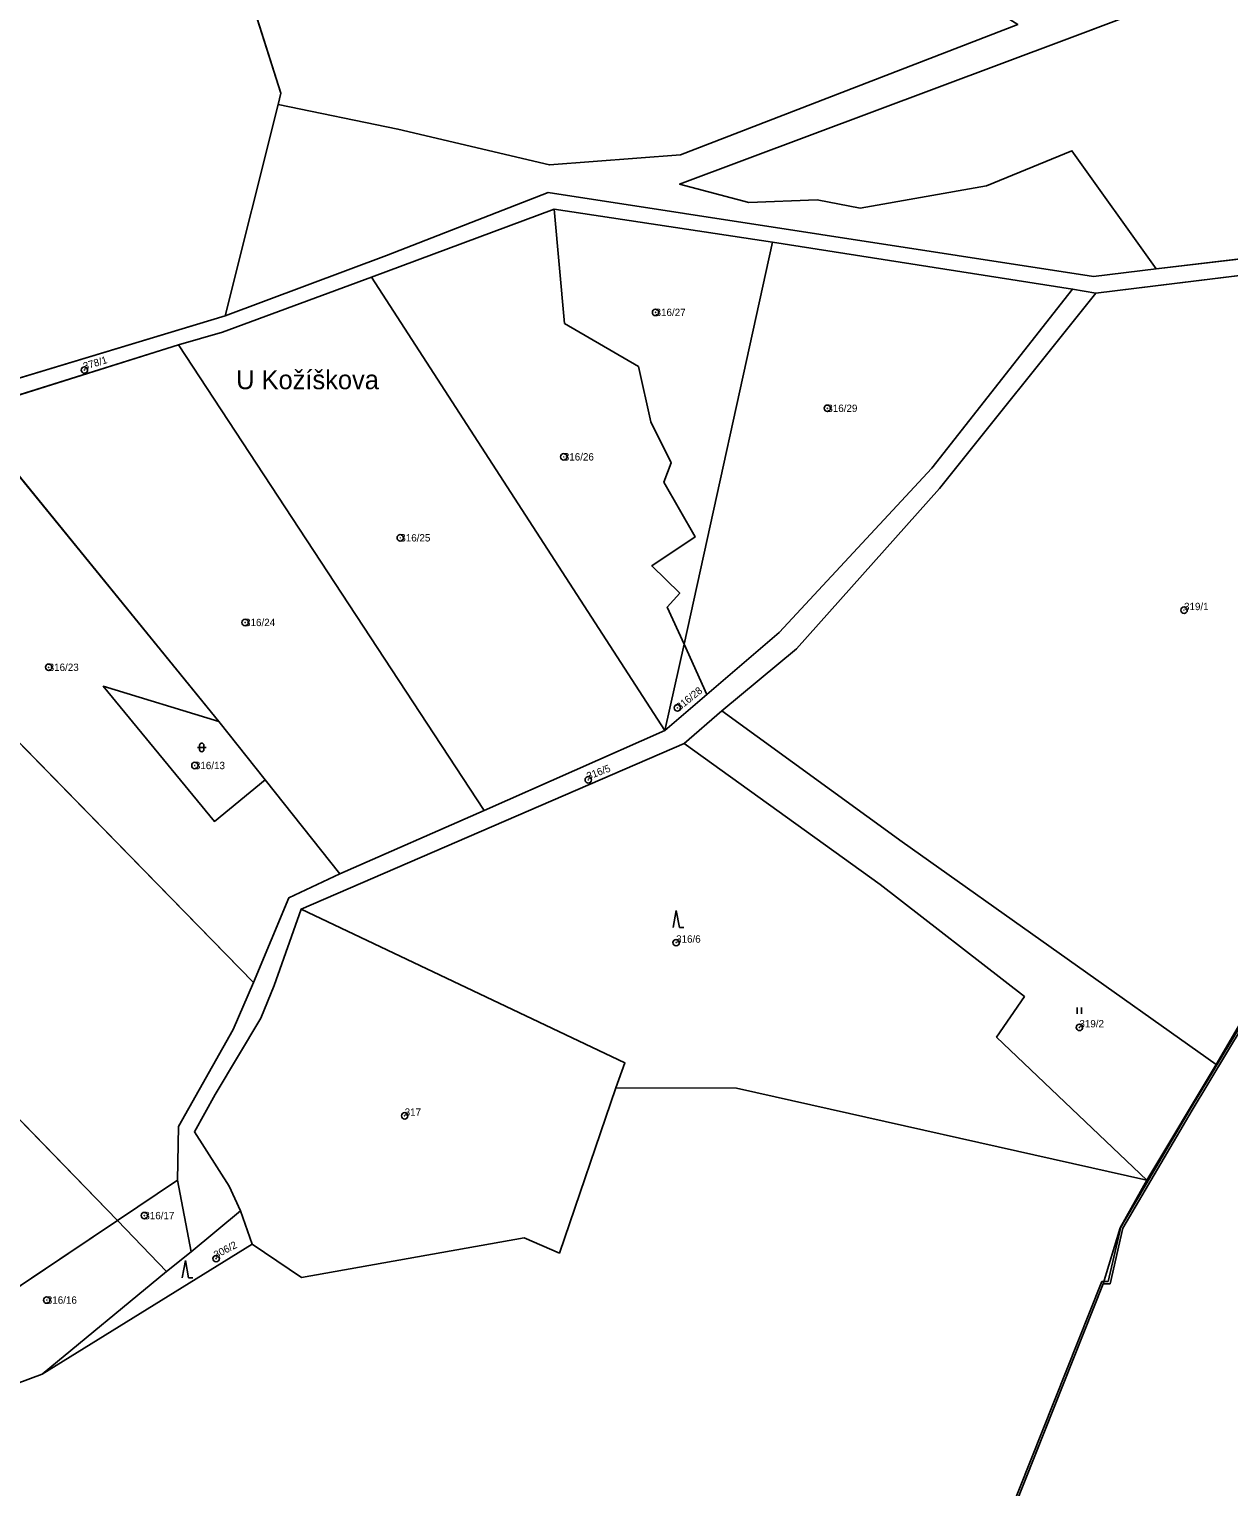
# Model space of a CAD drawing. Extents: x -652854 to -650068, y -1097661 to -1095417.
# Drawn here: x -651150.7 to -650873, y -1097423.6 to -1097086.2 of the extents above; entities that cross this region are included whole.
import ezdxf

# ---------------------------------------------------------------- set-up
doc = ezdxf.new("R2010")
doc.units = 0
for name, color, linetype in [('Definiční body parcel', 7, 'Continuous'), ('Hranice kat_ území', 7, 'Continuous'), ('Hranice parcel', 7, 'Continuous'), ('Názvy', 7, 'Continuous'), ('Obvody jako plochy', 7, 'Continuous'), ('Ostatní hranice', 7, 'Continuous'), ('Parcelní čísla', 7, 'Continuous'), ('Značky kultur', 7, 'Continuous')]:
    doc.layers.add(name, color=color, linetype=linetype)

msp = doc.modelspace()

# ---------------------------------------------------------------- linework, layer by layer
at = {"layer": 'Definiční body parcel'}
for centre, radius in [((-651005.7, -1097151.78), 0.75), ((-651005.7, -1097151.78), 0.0327), ((-651137.88, -1097165.12), 0.75), ((-651137.88, -1097165.12), 0.0327), ((-650965.95, -1097173.97), 0.75), ((-650965.95, -1097173.97), 0.0327), ((-651026.93, -1097185.21), 0.75), ((-651026.93, -1097185.21), 0.0327), ((-651064.77, -1097203.95), 0.75), ((-651064.77, -1097203.95), 0.0327), ((-651100.69, -1097223.54), 0.75), ((-650883.41, -1097220.69), 0.75), ((-650883.41, -1097220.69), 0.0327), ((-651100.69, -1097223.54), 0.0327), ((-651146.14, -1097233.91), 0.75), ((-651146.14, -1097233.91), 0.0327), ((-651000.65, -1097243.31), 0.75), ((-651000.65, -1097243.31), 0.0327), ((-651112.3, -1097256.64), 0.75), ((-651112.3, -1097256.64), 0.0327), ((-651021.27, -1097259.97), 0.75), ((-651021.27, -1097259.97), 0.0327), ((-651000.95, -1097297.64), 0.75), ((-651000.95, -1097297.64), 0.0327), ((-650907.62, -1097317.24), 0.75), ((-650907.62, -1097317.24), 0.0327), ((-651063.76, -1097337.7), 0.75), ((-651063.76, -1097337.7), 0.0327), ((-651124, -1097360.8), 0.75), ((-651124, -1097360.8), 0.0327), ((-651107.4, -1097370.77), 0.75), ((-651107.4, -1097370.77), 0.0327), ((-651146.57, -1097380.35), 0.75), ((-651146.57, -1097380.35), 0.0327)]:
    msp.add_circle(centre, radius, dxfattribs=at)
at = {"layer": 'Hranice kat_ území'}
for p, q in [((-650869.69, -1097316.78), (-650881.54, -1097336.4)), ((-650881.54, -1097336.4), (-650897.57, -1097363.68)), ((-650897.57, -1097363.68), (-650900.54, -1097376.56)), ((-650902.09, -1097376.6), (-650927.04, -1097439.3)), ((-650900.54, -1097376.56), (-650902.09, -1097376.6))]:
    msp.add_line(p, q, dxfattribs=at)
at = {"layer": 'Hranice parcel'}
for p, q in [((-651092.42, -1097101.02), (-651110.78, -1097043.06)), ((-650804.25, -1097048.49), (-650910.53, -1097088.56)), ((-650921.88, -1097085.12), (-650999.97, -1097115.32)), ((-650910.53, -1097088.56), (-651000.14, -1097122.08)), ((-651093.01, -1097103.7), (-651092.42, -1097101.02)), ((-651093.01, -1097103.7), (-651105.3, -1097152.59)), ((-651065.33, -1097109.35), (-651093.01, -1097103.7)), ((-651030.25, -1097117.65), (-651065.33, -1097109.35)), ((-650929.12, -1097122.49), (-650909.36, -1097114.39)), ((-650909.36, -1097114.39), (-650889.89, -1097141.73)), ((-650999.97, -1097115.32), (-651030.25, -1097117.65)), ((-651030.52, -1097124), (-651067.94, -1097138.65)), ((-650904.33, -1097143.45), (-651030.52, -1097124)), ((-651000.14, -1097122.08), (-650984.11, -1097126.35)), ((-650958.37, -1097127.66), (-650929.12, -1097122.49)), ((-651029.15, -1097127.92), (-651071.41, -1097143.63)), ((-651029.15, -1097127.92), (-651026.78, -1097154.34)), ((-650978.61, -1097135.56), (-651029.15, -1097127.92)), ((-650984.11, -1097126.35), (-650968.29, -1097125.74)), ((-650968.29, -1097125.74), (-650958.37, -1097127.66)), ((-650828.93, -1097134.46), (-650889.89, -1097141.73)), ((-651067.94, -1097138.65), (-651105.3, -1097152.59)), ((-650978.61, -1097135.56), (-650999.12, -1097228.58)), ((-650909.19, -1097146.38), (-650978.61, -1097135.56)), ((-650829.16, -1097138.13), (-650903.84, -1097147.32)), ((-650889.89, -1097141.73), (-650904.33, -1097143.45)), ((-651071.41, -1097143.63), (-651105.93, -1097156.36)), ((-651071.41, -1097143.63), (-651003.52, -1097248.52)), ((-650941.77, -1097187.84), (-650909.19, -1097146.38)), ((-650903.84, -1097147.32), (-650939.98, -1097192.57)), ((-650903.84, -1097147.32), (-650909.19, -1097146.38)), ((-651105.3, -1097152.59), (-651165.31, -1097170.68)), ((-651026.78, -1097154.34), (-651009.62, -1097164.32)), ((-651105.93, -1097156.36), (-651116.08, -1097159.28)), ((-651116.08, -1097159.28), (-651165.19, -1097174.72)), ((-651116.08, -1097159.28), (-651045.37, -1097267.07)), ((-651009.62, -1097164.32), (-651006.78, -1097177.08)), ((-651165.19, -1097174.72), (-651106.75, -1097246.46)), ((-651006.78, -1097177.08), (-651002.1, -1097186.58)), ((-651002.1, -1097186.58), (-651003.82, -1097191.08)), ((-650977.13, -1097225.83), (-650941.77, -1097187.84)), ((-651003.82, -1097191.08), (-650996.54, -1097203.75)), ((-650939.98, -1097192.57), (-650973.07, -1097229.61)), ((-651098.76, -1097306.87), (-651205.8, -1097197.3)), ((-650996.54, -1097203.75), (-651006.58, -1097210.44)), ((-651006.58, -1097210.44), (-651000.1, -1097216.76)), ((-651000.1, -1097216.76), (-651003, -1097220.02)), ((-651003, -1097220.02), (-650999.12, -1097228.58)), ((-650993.85, -1097240.21), (-650977.13, -1097225.83)), ((-650999.12, -1097228.58), (-651003.52, -1097248.52)), ((-650999.12, -1097228.58), (-650993.85, -1097240.21)), ((-650973.07, -1097229.61), (-650990.39, -1097244.02)), ((-651133.5, -1097238.3), (-651106.75, -1097246.46)), ((-651107.78, -1097269.59), (-651133.5, -1097238.3)), ((-651003.52, -1097248.52), (-650993.85, -1097240.21)), ((-651106.75, -1097246.46), (-651096.01, -1097259.99)), ((-650990.39, -1097244.02), (-650999.09, -1097251.52)), ((-650990.39, -1097244.02), (-650948.63, -1097274.32)), ((-651045.37, -1097267.07), (-651003.52, -1097248.52)), ((-650999.09, -1097251.52), (-651087.74, -1097289.88)), ((-650953.69, -1097284.17), (-650999.09, -1097251.52)), ((-651231.56, -1097257.41), (-651130.24, -1097361.96)), ((-651096.01, -1097259.99), (-651107.78, -1097269.59)), ((-651096.01, -1097259.99), (-651078.75, -1097281.73)), ((-651078.75, -1097281.73), (-651045.37, -1097267.07)), ((-650948.63, -1097274.32), (-650875.94, -1097325.81)), ((-651090.59, -1097287.26), (-651078.75, -1097281.73)), ((-651098.76, -1097306.87), (-651090.59, -1097287.26)), ((-650920.33, -1097310.11), (-650953.69, -1097284.17)), ((-651093.95, -1097307.59), (-651087.74, -1097289.88)), ((-651087.74, -1097289.88), (-651012.8, -1097325.46)), ((-650855.6, -1097291), (-650875.94, -1097325.81)), ((-651103.48, -1097317.72), (-651098.76, -1097306.87)), ((-651097.05, -1097315.13), (-651093.95, -1097307.59)), ((-650926.8, -1097319.53), (-650920.33, -1097310.11)), ((-651107.62, -1097332.76), (-651097.05, -1097315.13)), ((-651116.07, -1097340.17), (-651103.48, -1097317.72)), ((-650892.03, -1097352.57), (-650926.8, -1097319.53)), ((-651012.8, -1097325.46), (-651014.87, -1097331.26)), ((-650875.94, -1097325.81), (-650892.03, -1097352.57)), ((-651112.43, -1097341.42), (-651107.62, -1097332.76)), ((-651014.87, -1097331.26), (-651027.94, -1097369.47)), ((-651014.87, -1097331.26), (-650987.01, -1097331.29)), ((-650987.01, -1097331.29), (-650892.03, -1097352.57)), ((-651116.32, -1097352.64), (-651116.07, -1097340.17)), ((-651104.35, -1097354.01), (-651112.43, -1097341.42)), ((-651130.24, -1097361.96), (-651116.32, -1097352.64)), ((-651113.17, -1097369.2), (-651116.32, -1097352.64)), ((-651101.78, -1097359.68), (-651104.35, -1097354.01)), ((-650892.03, -1097352.57), (-650898.18, -1097363.61)), ((-651113.17, -1097369.2), (-651101.78, -1097359.68)), ((-651099.02, -1097367.38), (-651101.78, -1097359.68)), ((-651163.51, -1097384.26), (-651130.24, -1097361.96)), ((-651130.24, -1097361.96), (-651118.84, -1097373.75)), ((-650898.18, -1097363.61), (-650902.09, -1097376.6)), ((-651099.02, -1097367.38), (-651147.63, -1097397.5)), ((-651087.66, -1097375.14), (-651099.02, -1097367.38)), ((-651036.09, -1097365.97), (-651087.66, -1097375.14)), ((-651027.94, -1097369.47), (-651036.09, -1097365.97)), ((-651118.84, -1097373.75), (-651113.17, -1097369.2)), ((-651147.63, -1097397.5), (-651118.84, -1097373.75)), ((-651147.63, -1097397.5), (-651153.69, -1097399.75))]:
    msp.add_line(p, q, dxfattribs=at)
at = {"layer": 'Obvody jako plochy'}
for points in [[(-651105.3, -1097152.59), (-651093.01, -1097103.7), (-651092.42, -1097101.02), (-651110.78, -1097043.06), (-651093.83, -1097038.77), (-651072.08, -1097037.24), (-651052.68, -1097015.8), (-651005.44, -1097024.35), (-650984.81, -1096998.67), (-651046.91, -1096991.17), (-651079.38, -1096986.4), (-651123.24, -1096984.03), (-651223.1, -1097052.93), (-651170.2, -1097087.35), (-651161.42, -1097100.33), (-651159.02, -1097111.66), (-651169.04, -1097168.66), (-651165.31, -1097170.68)], [(-650999.97, -1097115.32), (-650921.88, -1097085.12), (-650957.85, -1097062.7), (-651013.59, -1097034.94), (-651025, -1097051.04), (-651054.64, -1097047.48), (-651110.78, -1097043.06), (-651092.42, -1097101.02), (-651093.01, -1097103.7), (-651065.33, -1097109.35), (-651030.25, -1097117.65)], [(-650773.96, -1097109.54), (-650775.22, -1097043.42), (-650804.25, -1097048.49), (-650910.53, -1097088.56), (-651000.14, -1097122.08), (-650984.11, -1097126.35), (-650968.29, -1097125.74), (-650958.37, -1097127.66), (-650929.12, -1097122.49), (-650909.36, -1097114.39), (-650889.89, -1097141.73), (-650828.93, -1097134.46), (-650799.57, -1097135.85), (-650754.48, -1097130.94)], [(-650754.48, -1097130.94), (-650799.57, -1097135.85), (-650828.93, -1097134.46), (-650889.89, -1097141.73), (-650904.33, -1097143.45), (-651030.52, -1097124), (-651067.94, -1097138.65), (-651105.3, -1097152.59), (-651165.31, -1097170.68), (-651176.11, -1097174.26), (-651173.63, -1097177.36), (-651165.19, -1097174.72), (-651116.08, -1097159.28), (-651105.93, -1097156.36), (-651071.41, -1097143.63), (-651029.15, -1097127.92), (-650978.61, -1097135.56), (-650909.19, -1097146.38), (-650903.84, -1097147.32), (-650829.16, -1097138.13), (-650798.48, -1097140.15), (-650747.6, -1097136.51)], [(-651029.15, -1097127.92), (-651071.41, -1097143.63), (-651003.52, -1097248.52), (-650999.12, -1097228.58), (-651003, -1097220.02), (-651000.1, -1097216.76), (-651006.58, -1097210.44), (-650996.54, -1097203.75), (-651003.82, -1097191.08), (-651002.1, -1097186.58), (-651006.78, -1097177.08), (-651009.62, -1097164.32), (-651026.78, -1097154.34)], [(-650978.61, -1097135.56), (-651029.15, -1097127.92), (-651026.78, -1097154.34), (-651009.62, -1097164.32), (-651006.78, -1097177.08), (-651002.1, -1097186.58), (-651003.82, -1097191.08), (-650996.54, -1097203.75), (-651006.58, -1097210.44), (-651000.1, -1097216.76), (-651003, -1097220.02), (-650999.12, -1097228.58)], [(-650977.13, -1097225.83), (-650941.77, -1097187.84), (-650909.19, -1097146.38), (-650978.61, -1097135.56), (-650999.12, -1097228.58), (-650993.85, -1097240.21)], [(-650771.9, -1097167.51), (-650747.6, -1097136.51), (-650798.48, -1097140.15), (-650829.16, -1097138.13), (-650903.84, -1097147.32), (-650939.98, -1097192.57), (-650973.07, -1097229.61), (-650990.39, -1097244.02), (-650948.63, -1097274.32), (-650875.94, -1097325.81), (-650855.6, -1097291), (-650824.97, -1097245.75)], [(-651105.93, -1097156.36), (-651116.08, -1097159.28), (-651045.37, -1097267.07), (-651003.52, -1097248.52), (-651071.41, -1097143.63)], [(-650903.84, -1097147.32), (-650909.19, -1097146.38), (-650941.77, -1097187.84), (-650977.13, -1097225.83), (-650993.85, -1097240.21), (-651003.52, -1097248.52), (-651045.37, -1097267.07), (-651078.75, -1097281.73), (-651090.59, -1097287.26), (-651098.76, -1097306.87), (-651103.48, -1097317.72), (-651116.07, -1097340.17), (-651116.32, -1097352.64), (-651113.17, -1097369.2), (-651101.78, -1097359.68), (-651104.35, -1097354.01), (-651112.43, -1097341.42), (-651107.62, -1097332.76), (-651097.05, -1097315.13), (-651093.95, -1097307.59), (-651087.74, -1097289.88), (-650999.09, -1097251.52), (-650990.39, -1097244.02), (-650973.07, -1097229.61), (-650939.98, -1097192.57)], [(-651116.08, -1097159.28), (-651165.19, -1097174.72), (-651106.75, -1097246.46), (-651096.01, -1097259.99), (-651078.75, -1097281.73), (-651045.37, -1097267.07)], [(-651098.76, -1097306.87), (-651090.59, -1097287.26), (-651078.75, -1097281.73), (-651096.01, -1097259.99), (-651107.78, -1097269.59), (-651133.5, -1097238.3), (-651106.75, -1097246.46), (-651165.19, -1097174.72), (-651173.63, -1097177.36), (-651205.8, -1097197.3)], [(-651116.07, -1097340.17), (-651103.48, -1097317.72), (-651098.76, -1097306.87), (-651205.8, -1097197.3), (-651222.78, -1097208.09), (-651199.19, -1097244.43), (-651231.56, -1097257.41), (-651130.24, -1097361.96), (-651116.32, -1097352.64)], [(-651003.52, -1097248.52), (-650993.85, -1097240.21), (-650999.12, -1097228.58)], [(-651106.75, -1097246.46), (-651133.5, -1097238.3), (-651107.78, -1097269.59), (-651096.01, -1097259.99)], [(-650953.69, -1097284.17), (-650920.33, -1097310.11), (-650926.8, -1097319.53), (-650892.03, -1097352.57), (-650875.94, -1097325.81), (-650948.63, -1097274.32), (-650990.39, -1097244.02), (-650999.09, -1097251.52)], [(-650953.69, -1097284.17), (-650999.09, -1097251.52), (-651087.74, -1097289.88), (-651012.8, -1097325.46), (-651014.87, -1097331.26), (-650987.01, -1097331.29), (-650892.03, -1097352.57), (-650926.8, -1097319.53), (-650920.33, -1097310.11)], [(-651163.51, -1097384.26), (-651130.24, -1097361.96), (-651231.56, -1097257.41), (-651233.9, -1097258.45), (-651226.5, -1097269.71), (-651234.23, -1097272.71)], [(-651027.94, -1097369.47), (-651014.87, -1097331.26), (-651012.8, -1097325.46), (-651087.74, -1097289.88), (-651093.95, -1097307.59), (-651097.05, -1097315.13), (-651107.62, -1097332.76), (-651112.43, -1097341.42), (-651104.35, -1097354.01), (-651101.78, -1097359.68), (-651099.02, -1097367.38), (-651087.66, -1097375.14), (-651036.09, -1097365.97)], [(-651130.24, -1097361.96), (-651118.84, -1097373.75), (-651113.17, -1097369.2), (-651116.32, -1097352.64)], [(-651147.63, -1097397.5), (-651099.02, -1097367.38), (-651101.78, -1097359.68), (-651113.17, -1097369.2), (-651118.84, -1097373.75)], [(-651163.51, -1097384.26), (-651153.69, -1097399.75), (-651147.63, -1097397.5), (-651118.84, -1097373.75), (-651130.24, -1097361.96)]]:
    msp.add_lwpolyline(points, close=True, dxfattribs=at)
for points in [[(-650921.88, -1097085.12), (-650999.97, -1097115.32), (-651030.25, -1097117.65), (-651065.33, -1097109.35), (-651093.01, -1097103.7), (-651105.3, -1097152.59), (-651067.94, -1097138.65), (-651030.52, -1097124), (-650904.33, -1097143.45), (-650889.89, -1097141.73), (-650909.36, -1097114.39), (-650929.12, -1097122.49), (-650958.37, -1097127.66), (-650968.29, -1097125.74), (-650984.11, -1097126.35), (-651000.14, -1097122.08), (-650910.53, -1097088.56), (-650804.25, -1097048.49)], [(-650927.04, -1097439.3), (-650902.09, -1097376.6), (-650898.18, -1097363.61), (-650892.03, -1097352.57), (-650987.01, -1097331.29), (-651014.87, -1097331.26), (-651027.94, -1097369.47), (-651036.09, -1097365.97), (-651087.66, -1097375.14), (-651099.02, -1097367.38), (-651147.63, -1097397.5), (-651153.69, -1097399.75), (-651205.61, -1097417.88), (-651214.96, -1097389.3), (-651219.49, -1097343.54), (-651231.23, -1097305.94), (-651238.43, -1097287.66), (-651245.02, -1097271.51), (-651259.51, -1097243.85), (-651276.57, -1097276.23), (-651292.83, -1097314.79), (-651311.99, -1097357.78)], [(-650855.6, -1097291), (-650875.94, -1097325.81), (-650892.03, -1097352.57), (-650898.18, -1097363.61), (-650902.09, -1097376.6), (-650900.54, -1097376.56), (-650897.57, -1097363.68), (-650881.54, -1097336.4), (-650869.69, -1097316.78)]]:
    msp.add_lwpolyline(points, dxfattribs=at)
at = {"layer": 'Ostatní hranice'}
for p, q in [((-650870.14, -1097316.54), (-650882.01, -1097336.19)), ((-650882.01, -1097336.19), (-650898.04, -1097363.47)), ((-650898.04, -1097363.47), (-650900.95, -1097376.07)), ((-650902.43, -1097376.09), (-650927.53, -1097439.13)), ((-650900.95, -1097376.07), (-650902.43, -1097376.09))]:
    msp.add_line(p, q, dxfattribs=at)
at = {"layer": 'Značky kultur'}
for p, q in [((-651111.71, -1097252.45), (-651109.71, -1097252.45)), ((-651111.21, -1097252.95), (-651111.21, -1097251.95)), ((-651110.21, -1097252.95), (-651110.21, -1097251.95)), ((-651000.912, -1097290.169), (-651001.645, -1097294.169)), ((-651000.912, -1097290.169), (-651000.179, -1097294.169)), ((-651000.179, -1097294.169), (-650999.179, -1097294.169)), ((-650908.127, -1097312.615), (-650908.127, -1097314.115)), ((-650907.105, -1097314.115), (-650907.105, -1097312.615)), ((-651114.482, -1097371.219), (-651115.215, -1097375.219)), ((-651114.482, -1097371.219), (-651113.749, -1097375.219)), ((-651113.749, -1097375.219), (-651112.749, -1097375.219))]:
    msp.add_line(p, q, dxfattribs=at)
for centre, start, end in [((-651110.71, -1097251.95), 0, 180), ((-651110.71, -1097252.95), 180, 0)]:
    msp.add_arc(centre, 0.5, start, end, dxfattribs=at)

# ---------------------------------------------------------------- texts
at = {"layer": 'Názvy'}
msp.add_text('U Kožíškova', height=4.4, dxfattribs=at).set_placement((-651102.76, -1097169.56))
at = {"layer": 'Parcelní čísla'}
for s, p in [('316/27', (-651005.7, -1097152.63)), ('316/29', (-650965.95, -1097174.82)), ('316/26', (-651026.93, -1097186.06)), ('316/25', (-651064.77, -1097204.8)), ('319/1', (-650883.41, -1097220.69)), ('316/24', (-651100.69, -1097224.39)), ('316/23', (-651146.14, -1097234.76)), ('316/13', (-651112.3, -1097257.49)), ('316/6', (-651000.95, -1097297.64)), ('319/2', (-650907.62, -1097317.24)), ('317', (-651063.76, -1097337.7)), ('316/17', (-651124, -1097361.65)), ('316/16', (-651146.57, -1097381.2))]:
    msp.add_text(s, height=1.7, dxfattribs=at).set_placement(p)
for s, rotation, p in [('378/1', 16.767, (-651137.88, -1097165.12)), ('316/28', 38.88, (-651000.116, -1097243.972)), ('316/5', 20.718, (-651021.27, -1097259.97)), ('306/2', 27.594, (-651107.4, -1097370.77))]:
    msp.add_text(s, height=1.7, rotation=rotation, dxfattribs=at).set_placement(p)

doc.saveas('drawing.dxf')
